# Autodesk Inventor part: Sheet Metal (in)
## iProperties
Shininess: 64.0
Length Units: 11272
Angle Units: 11279
Time Units: 11290
Mass Units: 11286
Length Display Precision: 3
Angle Display Precision: 2
Compacted: True
Part Number: Sheet Metal (in)
Document SubType Name: Sheet Metal
Created: 2002-07
Density: 1 g/cm^3
Density: 0.0
Volumn: 0.0
Area: 0.0
PropertySet Name: Model Information
Control State: 0
Master: False
Checked Out: False
